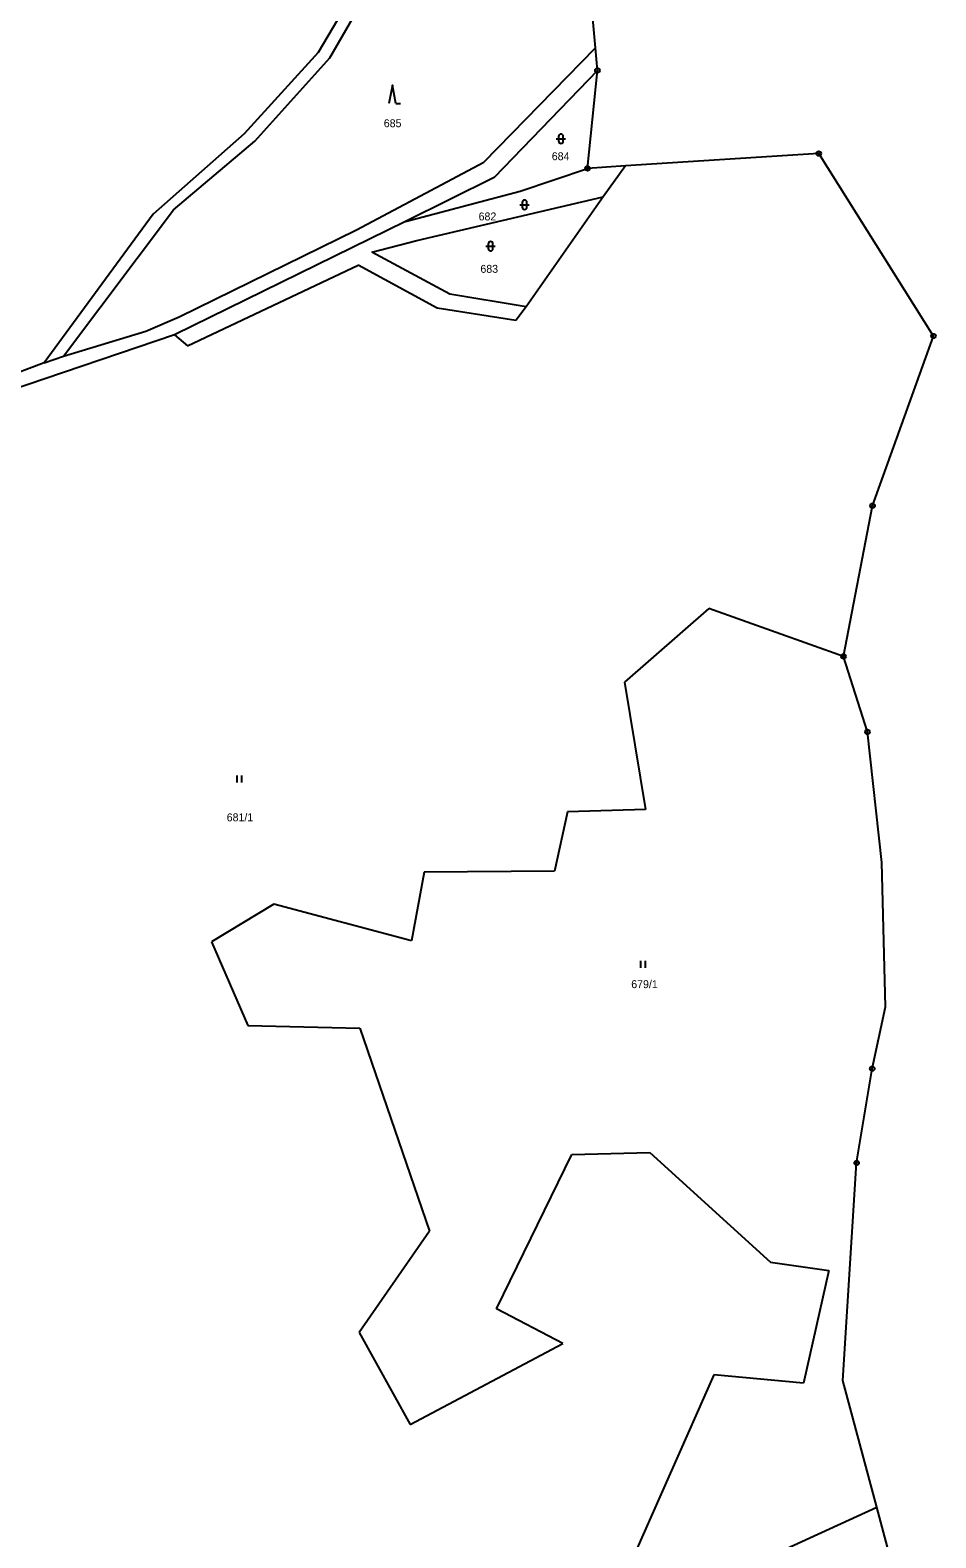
# Model space of a CAD drawing. Extents: x -744132 to -742433, y -984679 to -982287.
# Drawn here: x -742734.8 to -742540.1, y -982864.5 to -982540.5 of the extents above; entities that cross this region are included whole.
import ezdxf

# ---------------------------------------------------------------- set-up
doc = ezdxf.new("R2010")
doc.units = 0
doc.header["$LTSCALE"] = 0.68
for name, color, linetype, lineweight in [('1', 7, 'Continuous', 25), ('3', 7, 'Continuous', 25), ('8', 7, 'Continuous', 25)]:
    doc.layers.add(name, color=color, linetype=linetype, lineweight=lineweight)
doc.layers.add('2', color=7, linetype='Continuous')

msp = doc.modelspace()

# ---------------------------------------------------------------- linework, layer by layer
at = {"layer": '1'}
for p, q in [((-742655.09, -982514.99), (-742672.91, -982545.27)), ((-742670.35, -982546.43), (-742652.64, -982515.65)), ((-742613.28, -982544.25), (-742614.86, -982526)), ((-742637.26, -982568.8), (-742613.28, -982544.25)), ((-742612.86, -982549.12), (-742613.28, -982544.25)), ((-742672.91, -982545.27), (-742688.8, -982562.75)), ((-742686.47, -982564.28), (-742670.35, -982546.43)), ((-742612.86, -982549.12), (-742635.08, -982572.12)), ((-742614.97, -982570.16), (-742612.86, -982549.12)), ((-742688.8, -982562.75), (-742708.36, -982580.01)), ((-742704.01, -982579.08), (-742686.47, -982564.28)), ((-742565.29, -982566.98), (-742606.84, -982569.64)), ((-742540.62, -982606.19), (-742565.29, -982566.98)), ((-742664.68, -982583.39), (-742637.26, -982568.8)), ((-742629.46, -982575.06), (-742614.97, -982570.16)), ((-742606.84, -982569.64), (-742614.97, -982570.16)), ((-742606.84, -982569.64), (-742611.64, -982576.29)), ((-742635.08, -982572.12), (-742654.08, -982581.58)), ((-742654.08, -982581.58), (-742629.46, -982575.06)), ((-742651.66, -982585.69), (-742611.64, -982576.29)), ((-742611.64, -982576.29), (-742628.21, -982599.92)), ((-742708.36, -982580.01), (-742731.79, -982611.94)), ((-742727.64, -982610.54), (-742704.01, -982579.08)), ((-742654.08, -982581.58), (-742703.8, -982605.92)), ((-742702.78, -982602.09), (-742664.68, -982583.39)), ((-742661.36, -982588.16), (-742651.66, -982585.69)), ((-742644.6, -982597.23), (-742661.36, -982588.16)), ((-742700.98, -982608.3), (-742664.32, -982590.97)), ((-742647.3, -982600.2), (-742664.32, -982590.97)), ((-742628.21, -982599.92), (-742644.6, -982597.23)), ((-742709.93, -982605.17), (-742702.78, -982602.09)), ((-742630.38, -982602.87), (-742647.3, -982600.2)), ((-742628.21, -982599.92), (-742630.38, -982602.87)), ((-742703.8, -982605.92), (-742739.43, -982618.08)), ((-742727.64, -982610.54), (-742709.93, -982605.17)), ((-742703.8, -982605.92), (-742700.98, -982608.3)), ((-742553.71, -982642.66), (-742540.62, -982606.19)), ((-742731.79, -982611.94), (-742740.85, -982615.41)), ((-742731.79, -982611.94), (-742727.64, -982610.54)), ((-742559.97, -982675.06), (-742553.71, -982642.66)), ((-742588.94, -982664.75), (-742607.03, -982680.57)), ((-742559.97, -982675.06), (-742588.94, -982664.75)), ((-742554.81, -982691.28), (-742559.97, -982675.06)), ((-742607.03, -982680.57), (-742602.56, -982707.98)), ((-742551.72, -982719.36), (-742554.81, -982691.28)), ((-742619.3, -982708.48), (-742622.11, -982721.24)), ((-742602.56, -982707.98), (-742619.3, -982708.48)), ((-742650.11, -982721.44), (-742652.84, -982736.16)), ((-742622.11, -982721.24), (-742650.11, -982721.44)), ((-742550.91, -982750.37), (-742551.72, -982719.36)), ((-742682.41, -982728.33), (-742695.84, -982736.4)), ((-742652.84, -982736.16), (-742682.41, -982728.33)), ((-742695.84, -982736.4), (-742688.01, -982754.35)), ((-742553.8, -982763.66), (-742550.91, -982750.37)), ((-742688.01, -982754.35), (-742663.94, -982754.93)), ((-742663.94, -982754.93), (-742648.99, -982798.57)), ((-742557.14, -982783.92), (-742553.8, -982763.66)), ((-742634.57, -982815.24), (-742618.35, -982782.07)), ((-742618.35, -982782.07), (-742601.63, -982781.65)), ((-742601.63, -982781.65), (-742575.67, -982805.25)), ((-742560.1, -982830.67), (-742557.14, -982783.92)), ((-742648.99, -982798.57), (-742664.1, -982820.36)), ((-742575.67, -982805.25), (-742563.11, -982807.06)), ((-742563.11, -982807.06), (-742568.59, -982831.27)), ((-742620.28, -982822.71), (-742634.57, -982815.24)), ((-742664.1, -982820.36), (-742653.09, -982840.15)), ((-742653.09, -982840.15), (-742620.28, -982822.71)), ((-742587.81, -982829.47), (-742608.79, -982876.79)), ((-742568.59, -982831.27), (-742587.81, -982829.47)), ((-742552.79, -982857.93), (-742560.1, -982830.67)), ((-742692.17, -982921.38), (-742552.79, -982857.93)), ((-742545.32, -982885.8), (-742552.79, -982857.93))]:
    msp.add_line(p, q, dxfattribs=at)
at = {"layer": '3'}
for p, q in [((-742656.17, -982556.25), (-742655.174, -982556.25)), ((-742621.711, -982563.791), (-742619.709, -982563.791)), ((-742621.211, -982563.291), (-742621.211, -982564.292)), ((-742620.209, -982564.292), (-742620.209, -982563.291)), ((-742629.531, -982577.991), (-742627.529, -982577.991)), ((-742629.031, -982577.491), (-742629.031, -982578.492)), ((-742628.029, -982578.492), (-742628.029, -982577.491)), ((-742636.321, -982586.401), (-742636.321, -982587.402)), ((-742635.319, -982587.402), (-742635.319, -982586.401)), ((-742636.821, -982586.901), (-742634.819, -982586.901)), ((-742690.281, -982702.16), (-742690.281, -982700.66)), ((-742689.28, -982702.16), (-742689.28, -982700.66)), ((-742603.531, -982741.95), (-742603.531, -982740.45)), ((-742602.53, -982741.95), (-742602.53, -982740.45))]:
    msp.add_line(p, q, dxfattribs=at)
msp.add_lwpolyline([(-742656.17, -982556.25), (-742656.92, -982552.25), (-742657.67, -982556.25)], dxfattribs=at)
for centre, start, end in [((-742620.71, -982563.2909), 0, 180), ((-742620.71, -982564.2909), 180, 359.98789), ((-742628.53, -982577.4909), 0, 180), ((-742628.53, -982578.4909), 180, 359.98789), ((-742635.82, -982586.4009), 0, 180), ((-742635.82, -982587.4009), 180, 359.98789)]:
    msp.add_arc(centre, 0.5, start, end, dxfattribs=at)
at = {"layer": '8'}
for centre, radius in [((-742612.86, -982549.1199), 0.5), ((-742612.86, -982549.1199), 0.0303), ((-742565.29, -982566.9799), 0.5), ((-742565.29, -982566.9799), 0.0303), ((-742614.97, -982570.1599), 0.5), ((-742614.97, -982570.1599), 0.0303), ((-742540.62, -982606.1899), 0.5), ((-742540.62, -982606.1899), 0.0303), ((-742553.71, -982642.6599), 0.5), ((-742553.71, -982642.6599), 0.0303), ((-742559.97, -982675.0599), 0.5), ((-742559.97, -982675.0599), 0.0303), ((-742554.81, -982691.2799), 0.5), ((-742554.81, -982691.2799), 0.0303), ((-742553.8, -982763.6599), 0.5), ((-742553.8, -982763.6599), 0.0303), ((-742557.14, -982783.9199), 0.5), ((-742557.14, -982783.9199), 0.0303)]:
    msp.add_circle(centre, radius, dxfattribs=at)

# ---------------------------------------------------------------- texts
at = {"layer": '2'}
for s, p in [('685', (-742658.78, -982561.315)), ('684', (-742622.67, -982568.405)), ('682', (-742638.4, -982581.345)), ('683', (-742638.01, -982592.605)), ('681/1', (-742692.54, -982710.495)), ('679/1', (-742605.59, -982746.345))]:
    msp.add_text(s, height=1.7, dxfattribs=at).set_placement(p)

doc.saveas('drawing.dxf')
